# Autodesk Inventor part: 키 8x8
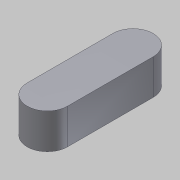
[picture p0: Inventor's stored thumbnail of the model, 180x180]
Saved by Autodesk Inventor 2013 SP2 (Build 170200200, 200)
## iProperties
Company: 한국ATC센터
Created: 2014-10
Part Number: 키 8x8
Document SubType Name: Modeling
Designer: 한국ATC센터
Density: 7.86 g/cm^3
Material: 강, 연강
Mass: 10.2483 g
Surface Area: 7.8646 cm^2
Volume: 1.30386 cm^3
Author: KYOUNG IL JANG
Revision Number: 1
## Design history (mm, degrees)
sketch "스케치1"
  geometry: L1 (28.264, -14)-(28.264, -31) reference; L2 (20.264, -31)-(20.264, -14) reference; A1 r 4 centre (24.264, -31) between (20.264, -31) and (28.264, -31) reference; A2 r 4 centre (24.264, -14) between (28.264, -14) and (20.264, -14) reference; 1 further point
extrude "돌출1" new body sketch "스케치1" distance "d0" = 7; taper "d1" = 0 deg
node "솔리드1"
node "참조1"
